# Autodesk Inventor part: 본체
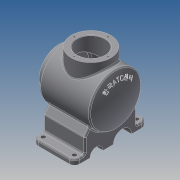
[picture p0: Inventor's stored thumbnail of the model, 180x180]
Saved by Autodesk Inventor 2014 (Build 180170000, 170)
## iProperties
Created: 2018-08
Part Number: 본체
Material: Generic
Document SubType Name: Modeling
Designer: kb542-19
Density: 1 g/cm^3
Appearance: Default
Author: kb542-19
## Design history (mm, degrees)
sketch "스케치1"
  geometry: L1 (-60, 0)-(60, 0); L2 (-60, 38)-(-48, 38); L3 (-48, 38)-(-48, 50); L4 (-48, 50)-(48.671, 50); L5 (-60, 38)-(-60, 27); L6 (-60, 27)-(-38, 27); L7 (-38, 27)-(-38, 40); L8 (-38, 40)-(42.163, 40); A1 r 116 centre (-56, 0) between (60, 0) and (48.671, 50); A2 r 106 centre (-56, 0) between (50, 0) and (42.163, 40); 2 further points
  constraints: 16 end point, 4 parallel, 4 point on circle, 3 perpendicular, 2 centre point, 1 coincident, 1 horizontal, 1 horizontal alignment, 1 midpoint, 1 point on line, 1 vertical alignment
  dimensions: "d0" = 116 radius of A1; "d2" = 100 diameter of L4 L1; "d3" = 12 distance of L2.start L2.end; "d4" = 108 distance from line of L1.end L3; "d5" = 54 diameter of L6 L1; "d6" = 76 diameter of L2 L1; "d7" = 22 distance of L5.end L6.end; "d8" = 10 radial gap between concentric circles of A1 A2; "d9" = 80 diameter of L8 L1
revolve "회전1" sketch "스케치1" stored, may be unused: angle "d10" = 90 deg
node "작업 평면1"
sketch "스케치2"
  geometry: L1 (-48, -50)-(-48, 50) reference; L2 (40, -70)-(-40, -70); L3 (-40, -70)-(-40, 70); L4 (-40, 70)-(40, 70); L5 (40, 70)-(40, -70); L6 (40, -70)-(-40, 70); L7 (-40, -70)-(40, 70); 3 further points
  constraints: 12 end point, 3 midpoint, 2 parallel, 1 coincident, 1 horizontal, 1 perpendicular
  dimensions: "d12" = 140 distance of L4.end L2.start; "d13" = 8 distance between parallel lines of L1 L3; "d14" = 80 distance of L2.start L2.end
extrude "돌출1" join sketch "스케치2" distance "d15" = 10; taper "d16" = 0 deg
fillet "모깎기1" dims "d17" = 10
sketch "스케치3"
  geometry: A1 r 10 centre (30, 60) between (40, 60) and (30, 70) reference; A2 r 10 centre (-30, 60) between (-30, 70) and (-40, 60) reference; A3 r 10 centre (-30, -60) between (-40, -60) and (-30, -70) reference; A4 r 10 centre (30, -60) between (30, -70) and (40, -60) reference; 5 further points
  constraints: 4 coincident
hole "구멍1" sketch "스케치3" at (-30, 60), (30, 60), (30, -60), (-30, -60) diameter "d18" = 8; stored, may be unused: countersink angle "d22" = 90 deg, drill point angle "d24" = 118 deg; dims "d19" = 6, "d20" = 4, "d21" = 2, "d23" = 8
sketch "스케치4"
  geometry: L1 (10, 120)-(10, 0) reference; L2 (0, 0)-(0, 120) reference; L3 (10, 110)-(38.563, 110); L4 (10, 130)-(0, 130) reference; L5 (10, 10)-(38.563, 10); L6 (0, -10)-(10, -10) reference; L7 (38.563, 110)-(52.41, 100.304); L8 (10, 130)-(38.563, 110); L9 (38.563, 10)-(52.41, 19.696); L10 (10, -10)-(38.563, 10); L11 (10, 0)-(10, 120) reference; L12 (10, 10)-(10, 110); C1 r 38 at (82, 60) reference; A1 r 50 centre (82, 60) between (52.41, 100.304) and (52.41, 19.696) reference; 1 further point
  constraints: 14 end point, 3 collinear, 2 point on circle, 2 point on line, 1 parallel, 1 perpendicular
  dimensions: "d25" = 20 distance between parallel lines of L4 L3; "d26" = 20 distance between parallel lines of L6 L5; "d28" = 35 deg angle of L4 L7; "d30" = 0 distance from line of L5.start L1; "d31" = 35 deg angle of L9 L6
extrude "돌출2" join sketch "스케치4" stored distance "d32" = 10; taper "d33" = 0 deg
node "작업 평면2"
sketch "스케치6"
  geometry: L1 (-48, -50)-(-48, 50) reference; C1 r 38 at (2, 0); 1 further point
  constraints: 1 centre point, 1 horizontal alignment
  dimensions: "d41" = 50 distance from line of L1 C1.centre; "d42" = 76 diameter of C1
extrude "돌출4" join sketch "스케치6" stored distance "d43" = 10; taper "d44" = 0 deg
sketch "스케치7"
  geometry: C1 r 38 at (0, 0) reference; C2 r 27 at (0, 0); 1 further point
  constraints: 1 centre point, 1 concentric
  dimensions: "d45" = 54 diameter of C2
extrude "돌출5" cut sketch "스케치7" stored distance "d46" = 10; taper "d47" = 0 deg
sketch "스케치8" dims "d48" = 65
  geometry: C1 r 27 at (0, 0) reference; C2 r 38 at (0, 0) reference; 3 further points
  constraints: 2 vertical alignment, 3 other
hole "구멍2" sketch "스케치8" at (0, 32.5) diameter "d49" = 3.242; stored, may be unused: countersink angle "d53" = 90 deg, drill point angle "d55" = 118 deg; dims "d50" = 8, "d51" = 4, "d52" = 2, "d54" = 10
sketch "스케치9"
  geometry: C1 r 38 at (0, 0) reference; 1 further point
  constraints: 1 horizontal alignment
  dimensions: "d59" = 32.5 distance of C1.centre point (32.5, 0)
hole "구멍3" sketch "스케치9" at (32.5, 0) diameter "d60" = 3.242; stored, may be unused: countersink angle "d64" = 90 deg, drill point angle "d66" = 118 deg; dims "d61" = 8, "d62" = 4, "d63" = 2, "d65" = 10
node "작업 평면3"
sketch "스케치10"
  geometry: C1 r 32.5 at (0, 0); 1 further point
  constraints: 1 centre point, 1 coincident, 1 other
  dimensions: "d71" = 65 diameter of C1
feature "엠보싱1" sketch "스케치10" dims "d12" = 140, "d13" = 8, "d14" = 80, "d72" = 0.5, "d73" = 0
fillet "모깎기2" dims "d74" = 3
chamfer "모따기1" distance "d75" = 1; stored, may be unused: second distance "d76" = 2, angle "d77" = 45 deg
fillet "모깎기3" dims "d78" = 3
fillet "모깎기4" dims "d79" = 3
fillet "모깎기5" dims "d80" = 3
sketch "스케치12"
  geometry: L1 (0, 120)-(0, 0) reference; C1 r 12.5 at (0, 32.5); C2 r 17.5 at (0, 82.5); A1 r 53 centre (-82, 60) between (-47.401, 19.851) and (-47.401, 100.149) reference
  constraints: 2 centre point, 2 point on line
  dimensions: "d81" = 27.5 vertical distance of A1.centre C1.centre; "d82" = 22.5 vertical distance of A1.centre C2.centre; "d83" = 25 diameter of C1; "d84" = 35 diameter of C2
extrude "돌출6" cut sketch "스케치12" stored distance "d85" = 10; taper "d86" = 0 deg
node "솔리드1"
pattern_circular "원형 패턴1" dims angle "d57" = 360 deg
pattern_circular "원형 패턴2" dims angle "d68" = 360 deg
node "투영된 루프1"
other parameters: "d11" = -82, "d27" = 35 deg, "d40" = -147, "d70" = -108
